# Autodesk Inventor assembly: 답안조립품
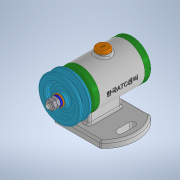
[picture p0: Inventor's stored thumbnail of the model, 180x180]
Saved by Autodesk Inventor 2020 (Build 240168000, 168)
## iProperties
Created: 2021-09
Part Number: 답안조립품
Document SubType Name: Assembly
Designer: Administrator
Author: Administrator
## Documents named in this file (14)
- C:\Users\Administrator\Desktop\710906V1023\답안조립품.iam
- C:\Users\Administrator\Desktop\710906V1023\본체.ipt
- C:\Users\Administrator\Desktop\710906V1023\축.ipt
- C:\Users\Administrator\Desktop\710906V1023\베어링 15x32x9.ipt
- C:\Users\Administrator\Desktop\710906V1023\앞커버.ipt
- C:\Users\Administrator\Desktop\710906V1023\뒤커버.ipt
- C:\Users\Administrator\Desktop\710906V1023\오일 실 15x25x7.ipt
- C:\Users\Administrator\Desktop\710906V1023\캡.ipt
- C:\Users\Administrator\Desktop\710906V1023\볼트 M4x12.ipt
- C:\Users\Administrator\Desktop\710906V1023\키 3x3.ipt
- C:\Users\Administrator\Desktop\710906V1023\V벨트풀리.ipt
- C:\Users\Administrator\Desktop\710906V1023\스프링와셔 8.ipt
- C:\Users\Administrator\Desktop\710906V1023\와셔 8x17.ipt
- C:\Users\Administrator\Desktop\710906V1023\너트 M8.ipt
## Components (1 placed, 1 different names)
1. V벨트풀리:1
